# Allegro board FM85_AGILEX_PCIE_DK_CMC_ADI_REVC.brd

Outline 254 x 111.15 mm; copper layers: TOP, L02_GND1, L03_SIG1, L04_GND2, L05_SIG2, L06_GND3, L07_SIG3, L08_GND4, L09_PWR1, L10_PWR2, L11_GND5, L12_SIG4, L13_GND6, L14_SIG5, L15_GND7, L16_SIG6, L17_GND8, BOTTOM. Coordinates in mm from the lower left corner of the outline.
Outline path: 0,111.15 0,4.5 15,4.5 15,12.75 33.35,12.75 33.35,4.5 41.35,4.5 41.35,10.92 arc(43.18,12.75) 45,10.92 45,0.5 45.5,0 55.7,0 56.2,0.5 56.2,7.45 arc(57.15,8.4) 58.1,7.45 58.1,0.5 58.6,0 128.8,0 129.3,0.5 129.3,7.62 arc(130.67,8.99) 132.04,7.62 132.04,3.45 132.55,2.95 143.35,2.95 144.74,5.32 144.74,7.95 140.78,7.95 arc(139.54,8.46) 139.03,9.7 139.03,11 arc(139.54,12.24) 140.78,12.75 254,12.75 254,111.15 0,111.15

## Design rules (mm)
constraint set DEFAULT: min track width 0.149
net group AVST8_CLK: nets AVST8_CLK AVST8_CLK_R
net group BMC_BUF_TCK: nets BMC_BUF_TCK N40362434
net group BMC_BUF_TDI: nets BMC_BUF_TDI N40362458
net group BMC_BUF_TMS: nets BMC_BUF_TMS N40362320
net group BUF1_Q0_N: nets BUF1_Q0_N REFCLK_PCIE_14C_CH0_N
net group BUF1_Q0_P: nets BUF1_Q0_P REFCLK_PCIE_14C_CH0_P
net group BUF1_Q1_N: nets BUF1_Q1_N REFCLK_PCIE_14C_CH1_N
net group BUF1_Q1_P: nets BUF1_Q1_P REFCLK_PCIE_14C_CH1_P
net group BUF2_Q0_N: nets BUF2_Q0_N REFCLK_CXL_15C_CH0_N
net group BUF2_Q0_P: nets BUF2_Q0_P REFCLK_CXL_15C_CH0_P
net group BUF2_Q1_N: nets BUF2_Q1_N REFCLK_CXL_15C_CH1_N
net group BUF2_Q1_P: nets BUF2_Q1_P REFCLK_CXL_15C_CH1_P
net group BUF2_Q2_N: nets BUF2_Q2_N REFCLK_FM41_15C_CXL_N
net group BUF2_Q2_P: nets BUF2_Q2_P REFCLK_FM41_15C_CXL_P
net group CLK_DDR4: nets CLK_DDR4_CH1_N CLK_DDR4_CH1_P
net group CLK_DDR4_CH0_N: nets CLK_DDR4_CH0_N SI5391_OUT2N
net group CLK_DDR4_CH0_P: nets CLK_DDR4_CH0_P SI5391_OUT2P
net group CLK_DDR4_CH2_N: nets CLK_DDR4_CH2_N SI5391_OUT1N
net group CLK_DDR4_CH2_P: nets CLK_DDR4_CH2_P SI5391_OUT1P
net group CLK_SYS_100M_N: nets CLK_SYS_100M_N SI5391_OUT9N
net group CLK_SYS_100M_P: nets CLK_SYS_100M_P SI5391_OUT9P
net group CXL_TX_C_N0: nets CXL_TX_C_N0 CXL_TX_N0
net group CXL_TX_C_N1: nets CXL_TX_C_N1 CXL_TX_N1
net group CXL_TX_C_N2: nets CXL_TX_C_N2 CXL_TX_N2
net group CXL_TX_C_N3: nets CXL_TX_C_N3 CXL_TX_N3
net group CXL_TX_C_N4: nets CXL_TX_C_N4 CXL_TX_N4
net group CXL_TX_C_N5: nets CXL_TX_C_N5 CXL_TX_N5
net group CXL_TX_C_N6: nets CXL_TX_C_N6 CXL_TX_N6
net group CXL_TX_C_N7: nets CXL_TX_C_N7 CXL_TX_N7
net group CXL_TX_C_N8: nets CXL_TX_C_N8 CXL_TX_N8
net group CXL_TX_C_N9: nets CXL_TX_C_N9 CXL_TX_N9
net group CXL_TX_C_N10: nets CXL_TX_C_N10 CXL_TX_N10
net group CXL_TX_C_N11: nets CXL_TX_C_N11 CXL_TX_N11
net group CXL_TX_C_N12: nets CXL_TX_C_N12 CXL_TX_N12
net group CXL_TX_C_N13: nets CXL_TX_C_N13 CXL_TX_N13
net group CXL_TX_C_N14: nets CXL_TX_C_N14 CXL_TX_N14
net group CXL_TX_C_N15: nets CXL_TX_C_N15 CXL_TX_N15
net group CXL_TX_C_P0: nets CXL_TX_C_P0 CXL_TX_P0
net group CXL_TX_C_P1: nets CXL_TX_C_P1 CXL_TX_P1
net group CXL_TX_C_P2: nets CXL_TX_C_P2 CXL_TX_P2
net group CXL_TX_C_P3: nets CXL_TX_C_P3 CXL_TX_P3
net group CXL_TX_C_P4: nets CXL_TX_C_P4 CXL_TX_P4
net group CXL_TX_C_P5: nets CXL_TX_C_P5 CXL_TX_P5
net group CXL_TX_C_P6: nets CXL_TX_C_P6 CXL_TX_P6
net group CXL_TX_C_P7: nets CXL_TX_C_P7 CXL_TX_P7
net group CXL_TX_C_P8: nets CXL_TX_C_P8 CXL_TX_P8
net group CXL_TX_C_P9: nets CXL_TX_C_P9 CXL_TX_P9
net group CXL_TX_C_P10: nets CXL_TX_C_P10 CXL_TX_P10
net group CXL_TX_C_P11: nets CXL_TX_C_P11 CXL_TX_P11
net group CXL_TX_C_P12: nets CXL_TX_C_P12 CXL_TX_P12
net group CXL_TX_C_P13: nets CXL_TX_C_P13 CXL_TX_P13
net group CXL_TX_C_P14: nets CXL_TX_C_P14 CXL_TX_P14
net group CXL_TX_C_P15: nets CXL_TX_C_P15 CXL_TX_P15
net group DDR4_DDIMM2_C0: nets DDR4_DDIMM2_C0 DDR4_DDIMM2_C0_CS_N2
net group DDR4_DDIMM_C0: nets DDR4_DDIMM_C0 DDR4_DDIMM_C0_CS_N2
net group DP39: nets DDR4_DDIMM_CK_N1 DDR4_DDIMM_CK_P1
net group DP41: nets REFCLK_FM41_14C_PCIE_N REFCLK_FM41_14C_PCIE_P
net group DP_DDR3B_DQS_6: nets DDR4_COMP_CH0_DQS_P3 DDR4_DDIMM2_DQS_P1
net group DP_FX2_D_: nets FX2_D_N FX2_D_P
net group DP_N4110735: nets N41107356 N41107358
net group DP_PEX_RX_0: nets PCIE_EP_TX_N0 PCIE_EP_TX_P0
net group DP_PEX_RX_1: nets PCIE_EP_TX_N1 PCIE_EP_TX_P1
net group DP_PEX_RX_2: nets PCIE_EP_TX_N2 PCIE_EP_TX_P2
net group DP_PEX_RX_3: nets PCIE_EP_TX_N3 PCIE_EP_TX_P3
net group DP_PEX_RX_4: nets PCIE_EP_TX_N4 PCIE_EP_TX_P4
net group DP_PEX_RX_5: nets PCIE_EP_TX_N5 PCIE_EP_TX_P5
net group DP_PEX_RX_6: nets PCIE_EP_TX_N6 PCIE_EP_TX_P6
net group DP_PEX_RX_7: nets PCIE_EP_TX_N7 PCIE_EP_TX_P7
net group DP_PEX_RX_8: nets PCIE_EP_TX_N8 PCIE_EP_TX_P8
net group DP_PEX_RX_9: nets PCIE_EP_TX_N9 PCIE_EP_TX_P9
net group DP_PEX_RX_10: nets PCIE_EP_TX_N10 PCIE_EP_TX_P10
net group DP_PEX_RX_11: nets PCIE_EP_TX_N11 PCIE_EP_TX_P11
net group DP_PEX_RX_12: nets PCIE_EP_TX_N12 PCIE_EP_TX_P12
net group DP_PEX_RX_13: nets PCIE_EP_TX_N13 PCIE_EP_TX_P13
net group DP_PEX_RX_14: nets PCIE_EP_TX_N14 PCIE_EP_TX_P14
net group DP_PEX_RX_15: nets PCIE_EP_TX_N15 PCIE_EP_TX_P15
net group FM6_TEMP1: nets FPGA_TEMP1N FPGA_TEMP1P
net group FM6_TEMP3: nets FPGA_TEMP3N FPGA_TEMP3P
net group FPGA_TEMP0A: nets FPGA_TEMP0AN FPGA_TEMP0AP
net group FPGA_TEMP0C: nets FPGA_TEMP0CN FPGA_TEMP0CP
net group FPGA_TEMP4: nets FPGA_TEMP4N FPGA_TEMP4P
net group FPGA_TEMP6: nets FPGA_TEMP6N FPGA_TEMP6P
net group GNDSENSE: nets GNDSENSE VSENSE0-
net group HPS_OSC_CLK: nets HPS_OSC_CLK SI5391_OUT9A
net group HRAM_CK: nets HRAM_CK HRAM_CK_R
net group HRAM_CK_N: nets HRAM_CK_N HRAM_CK_N_R
net group HRAM_CS: nets HRAM_CS HRAM_CS_R
net group HRAM_D0: nets HRAM_D0 N46887455
net group HRAM_D1: nets HRAM_D1 N46887476
net group HRAM_D2: nets HRAM_D2 N46887502
net group HRAM_D3: nets HRAM_D3 N46887527
net group HRAM_D4: nets HRAM_D4 N46887553
net group HRAM_D5: nets HRAM_D5 N46887581
net group HRAM_D6: nets HRAM_D6 N46887604
net group HRAM_D7: nets HRAM_D7 N46887630
net group I2C2: nets I2C2_SCL I2C2_SDA
net group I2C3: nets I2C3_SCL I2C3_SDA
net group MG2: nets DDR4_DDIMM_CK_N0 DDR4_DDIMM_CK_P0
net group N32053041: nets N32052935 N32053041
net group N40226164: nets N40226161 N40226164
net group N40710315: nets N40710194 N40710315
net group N41064487: nets N41064487 N41064609
net group PCIE_EP_JTAG_TDO: nets N40362341 PCIE_EP_JTAG_TDO
net group PCIE_EP_RX_CN0: nets PCIE_EP_RX_CN0 PCIE_EP_RX_N0
net group PCIE_EP_RX_CN1: nets PCIE_EP_RX_CN1 PCIE_EP_RX_N1
net group PCIE_EP_RX_CN2: nets PCIE_EP_RX_CN2 PCIE_EP_RX_N2
net group PCIE_EP_RX_CN3: nets PCIE_EP_RX_CN3 PCIE_EP_RX_N3
net group PCIE_EP_RX_CN4: nets PCIE_EP_RX_CN4 PCIE_EP_RX_N4
net group PCIE_EP_RX_CN5: nets PCIE_EP_RX_CN5 PCIE_EP_RX_N5
net group PCIE_EP_RX_CN6: nets PCIE_EP_RX_CN6 PCIE_EP_RX_N6
net group PCIE_EP_RX_CN7: nets PCIE_EP_RX_CN7 PCIE_EP_RX_N7
net group PCIE_EP_RX_CN8: nets PCIE_EP_RX_CN8 PCIE_EP_RX_N8
net group PCIE_EP_RX_CN9: nets PCIE_EP_RX_CN9 PCIE_EP_RX_N9
net group PCIE_EP_RX_CN10: nets PCIE_EP_RX_CN10 PCIE_EP_RX_N10
net group PCIE_EP_RX_CN11: nets PCIE_EP_RX_CN11 PCIE_EP_RX_N11
net group PCIE_EP_RX_CN12: nets PCIE_EP_RX_CN12 PCIE_EP_RX_N12
net group PCIE_EP_RX_CN13: nets PCIE_EP_RX_CN13 PCIE_EP_RX_N13
net group PCIE_EP_RX_CN14: nets PCIE_EP_RX_CN14 PCIE_EP_RX_N14
net group PCIE_EP_RX_CN15: nets PCIE_EP_RX_CN15 PCIE_EP_RX_N15
net group PCIE_EP_RX_CP0: nets PCIE_EP_RX_CP0 PCIE_EP_RX_P0
net group PCIE_EP_RX_CP1: nets PCIE_EP_RX_CP1 PCIE_EP_RX_P1
net group PCIE_EP_RX_CP2: nets PCIE_EP_RX_CP2 PCIE_EP_RX_P2
net group PCIE_EP_RX_CP3: nets PCIE_EP_RX_CP3 PCIE_EP_RX_P3
net group PCIE_EP_RX_CP4: nets PCIE_EP_RX_CP4 PCIE_EP_RX_P4
net group PCIE_EP_RX_CP5: nets PCIE_EP_RX_CP5 PCIE_EP_RX_P5
net group PCIE_EP_RX_CP6: nets PCIE_EP_RX_CP6 PCIE_EP_RX_P6
net group PCIE_EP_RX_CP7: nets PCIE_EP_RX_CP7 PCIE_EP_RX_P7
net group PCIE_EP_RX_CP8: nets PCIE_EP_RX_CP8 PCIE_EP_RX_P8
net group PCIE_EP_RX_CP9: nets PCIE_EP_RX_CP9 PCIE_EP_RX_P9
net group PCIE_EP_RX_CP10: nets PCIE_EP_RX_CP10 PCIE_EP_RX_P10
net group PCIE_EP_RX_CP11: nets PCIE_EP_RX_CP11 PCIE_EP_RX_P11
net group PCIE_EP_RX_CP12: nets PCIE_EP_RX_CP12 PCIE_EP_RX_P12
net group PCIE_EP_RX_CP13: nets PCIE_EP_RX_CP13 PCIE_EP_RX_P13
net group PCIE_EP_RX_CP14: nets PCIE_EP_RX_CP14 PCIE_EP_RX_P14
net group PCIE_EP_RX_CP15: nets PCIE_EP_RX_CP15 PCIE_EP_RX_P15
net group REFCLK_CXL_RP_N0: nets REFCLK_CXL_RP_N0 SI2204_OUT2N
net group REFCLK_CXL_RP_N1: nets REFCLK_CXL_RP_N1 SI2204_OUT3N
net group REFCLK_CXL_RP_P0: nets REFCLK_CXL_RP_P0 SI2204_OUT2P
net group REFCLK_CXL_RP_P1: nets REFCLK_CXL_RP_P1 SI2204_OUT3P
net group REFCLK_FGT12ACH0_N: nets REFCLK_FGT12ACH0_N SI5391_OUT8N
net group REFCLK_FGT12ACH0_P: nets REFCLK_FGT12ACH0_P SI5391_OUT8P
net group REFCLK_FGT12ACH3_N: nets REFCLK_FGT12ACH3_N SI5391_OUT6N
net group REFCLK_FGT12ACH3_P: nets REFCLK_FGT12ACH3_P SI5391_OUT6P
net group REFCLK_FGT12ACH4_N: nets REFCLK_FGT12ACH4_N SI5391_OUT0N
net group REFCLK_FGT12ACH4_P: nets REFCLK_FGT12ACH4_P SI5391_OUT0P
net group REFCLK_FGT12ACH5_N: nets REFCLK_FGT12ACH5_N SI5391_OUT0AN
net group REFCLK_FGT12ACH5_P: nets REFCLK_FGT12ACH5_P SI5391_OUT0AP
net group REFCLK_FGT12ACH6_N: nets REFCLK_FGT12ACH6_N SI5391_OUT4N
net group REFCLK_FGT12ACH6_P: nets REFCLK_FGT12ACH6_P SI5391_OUT4P
net group REFCLK_PCIE_EP_EDGE_N: nets BUF1_CLK0_N REFCLK_PCIE_EP_EDGE_N
net group REFCLK_PCIE_EP_EDGE_P: nets BUF1_CLK0_P REFCLK_PCIE_EP_EDGE_P
net group USB_T_CLK: nets N49230785 USB_T_CLK
net group VCCED_SNS_P: nets VCCED_SNS_N VCCED_SNS_P
net group VCCL_HPS_SNS_P: nets VCCL_HPS_SNS_N VCCL_HPS_SNS_P
net group VCCLSENSE: nets VCCLSENSE VSENSE0+
net group 5MILS: nets 1P2V_DDR4_CH01_PG 1P8V_EN 1P8V_PG 2P5V_EN 2P5V_PG 3P3V_EN 3P3V_PG 5V_PG 12V_G1_OV_PG 12V_G1_PG 12V_G1_UV_PG 12V_G2_PG FPGA_I2C_EN FPGA_PMBUS_EN FPGA_VCC_EN FPGA_VCC_PG IO_1P8V_EN IO_1P8V_PG IO_3P3V_EN MAIN_PMBUS_EN VCCFUSEWR_EN VCCFUSEWR_PG VCCL_HPS_EN VCCL_HPS_PG
net group 8MILS: nets N32408441 N40710340 N45054348 N45054411 N45054431 N45054433 N45054466 N45054537 N45054575 N45054598 N45054651 N45054838 N45056577 N45056642 N45056662 N45056664 N45056697 N45056806 N45056829 N45056882 N45057066
net group 12V_PWR: nets 12V_AUX 12V_G2 12V_GROUP1 12V_GROUP2 PCIE_EP_12V
net group 42.5 OHM OUT: nets N37651435 N37651438 N37651441 N37651444 N37651447 N37651450 N37651453 N37651456 N37651459 N37651462 N37651465 PCIE_CLKREQN PCIE_EP_PRSNT_NX1 PCIE_EP_PRSNT_NX4 PCIE_EP_PRSNT_NX8 PCIE_EP_PRSNT_NX16 PCIE_PWRBRKN PCIE_RSV2 PCIE_RSV4 PCIE_RSV5 PCIE_RSV6 PCIE_RSV7
net group BUF1_CLK1_N: nets BUF1_CLK1_N REFCLK_PCIE_EP_N SI2204_OUT0N
net group BUF1_CLK1_P: nets BUF1_CLK1_P REFCLK_PCIE_EP_P SI2204_OUT0P
net group BUF2_CLK0_N: nets BUF2_CLK0_N CLK_100M_CXL_CONN_C_N CLK_CXL_CONN_N
net group BUF2_CLK0_P: nets BUF2_CLK0_P CLK_100M_CXL_CONN_C_P CLK_CXL_CONN_P
net group BUF2_CLK1_N: nets BUF2_CLK1_N REFCLK_CXL_EP_N SI2204_OUT1N
net group BUF2_CLK1_P: nets BUF2_CLK1_P REFCLK_CXL_EP_P SI2204_OUT1P
net group CLK: nets SI5391_OUT3N SI5391_OUT3P SI5391_OUT5N SI5391_OUT5P
net group CLK_SE: nets DDR4_DIMM_SCL DDR4_DIMM_SDA FPGA_OSC_CLK_1 FPGA_SDM_SCL FPGA_SDM_SDA PCIE_1V2_CLKREQN PCIE_EP_SMBCLK SEL_CXL_REFCLK SEL_PCIE_REFCLK
net group CXL_RX: nets CXL_RX_N0 CXL_RX_N1 CXL_RX_N2 CXL_RX_N3 CXL_RX_N5 CXL_RX_N6 CXL_RX_N7 CXL_RX_N9 CXL_RX_N10 CXL_RX_N11 CXL_RX_N12 CXL_RX_N13 CXL_RX_N15 CXL_RX_P0 CXL_RX_P1 CXL_RX_P2 CXL_RX_P3 CXL_RX_P5 CXL_RX_P6 CXL_RX_P7 CXL_RX_P9 CXL_RX_P10 CXL_RX_P11 CXL_RX_P12 CXL_RX_P13 CXL_RX_P15
net group DDR: nets DDR4_COMP_CH0_A1 DDR4_COMP_CH0_A2 DDR4_COMP_CH0_A3 DDR4_COMP_CH0_A4 DDR4_COMP_CH0_A5 DDR4_COMP_CH0_A6 DDR4_COMP_CH0_A7 DDR4_COMP_CH0_A8 DDR4_COMP_CH0_A9 DDR4_COMP_CH0_A10 DDR4_COMP_CH0_A11 DDR4_COMP_CH0_A12 DDR4_COMP_CH0_A13 DDR4_COMP_CH0_A14 DDR4_COMP_CH0_A15 DDR4_COMP_CH0_A16 DDR4_COMP_CH0_ACT_N DDR4_COMP_CH0_ALERT_N DDR4_COMP_CH0_BA0 DDR4_COMP_CH0_BA1 DDR4_COMP_CH0_BG0 DDR4_COMP_CH0_BG1 DDR4_COMP_CH0_CLK_N DDR4_COMP_CH0_CS_N DDR4_COMP_CH0_DBI_N0 DDR4_COMP_CH0_DBI_N1 DDR4_COMP_CH0_DBI_N2 DDR4_COMP_CH0_DBI_N3 DDR4_COMP_CH0_DBI_N4 DDR4_COMP_CH0_DBI_N5 DDR4_COMP_CH0_DBI_N6 DDR4_COMP_CH0_DBI_N7 DDR4_COMP_CH0_DBI_N8 DDR4_COMP_CH0_DQ0 DDR4_COMP_CH0_DQ1 DDR4_COMP_CH0_DQ2 DDR4_COMP_CH0_DQ3 DDR4_COMP_CH0_DQ4 DDR4_COMP_CH0_DQ5 DDR4_COMP_CH0_DQ6 DDR4_COMP_CH0_DQ7 DDR4_COMP_CH0_DQ8 DDR4_COMP_CH0_DQ9 DDR4_COMP_CH0_DQ10 DDR4_COMP_CH0_DQ11 DDR4_COMP_CH0_DQ12 DDR4_COMP_CH0_DQ13 DDR4_COMP_CH0_DQ14 DDR4_COMP_CH0_DQ15 DDR4_COMP_CH0_DQ16 DDR4_COMP_CH0_DQ17 DDR4_COMP_CH0_DQ18 DDR4_COMP_CH0_DQ19 DDR4_COMP_CH0_DQ20 DDR4_COMP_CH0_DQ21 DDR4_COMP_CH0_DQ22 DDR4_COMP_CH0_DQ23 DDR4_COMP_CH0_DQ24 DDR4_COMP_CH0_DQ25 DDR4_COMP_CH0_DQ26 DDR4_COMP_CH0_DQ27 DDR4_COMP_CH0_DQ28 DDR4_COMP_CH0_DQ29 DDR4_COMP_CH0_DQ30 DDR4_COMP_CH0_DQ31 DDR4_COMP_CH0_DQ32 DDR4_COMP_CH0_DQ33 DDR4_COMP_CH0_DQ34 DDR4_COMP_CH0_DQ35 DDR4_COMP_CH0_DQ36 DDR4_COMP_CH0_DQ37 DDR4_COMP_CH0_DQ38 DDR4_COMP_CH0_DQ39 DDR4_COMP_CH0_DQ40 DDR4_COMP_CH0_DQ41 DDR4_COMP_CH0_DQ42 DDR4_COMP_CH0_DQ43 DDR4_COMP_CH0_DQ44 DDR4_COMP_CH0_DQ45 DDR4_COMP_CH0_DQ46 DDR4_COMP_CH0_DQ47 DDR4_COMP_CH0_DQ48 DDR4_COMP_CH0_DQ49 DDR4_COMP_CH0_DQ50 DDR4_COMP_CH0_DQ51 DDR4_COMP_CH0_DQ52 DDR4_COMP_CH0_DQ53 DDR4_COMP_CH0_DQ54 DDR4_COMP_CH0_DQ55 DDR4_COMP_CH0_DQ56 DDR4_COMP_CH0_DQ57 DDR4_COMP_CH0_DQ58 DDR4_COMP_CH0_DQ59 DDR4_COMP_CH0_DQ60 DDR4_COMP_CH0_DQ61 DDR4_COMP_CH0_DQ62 DDR4_COMP_CH0_DQ63 DDR4_COMP_CH0_DQ64 DDR4_COMP_CH0_DQ65 DDR4_COMP_CH0_DQ66 DDR4_COMP_CH0_DQ67 DDR4_COMP_CH0_DQ68 DDR4_COMP_CH0_DQ69 DDR4_COMP_CH0_DQ70 DDR4_COMP_CH0_DQ71 DDR4_COMP_CH0_DQS_N0 DDR4_COMP_CH0_DQS_N1 DDR4_COMP_CH0_DQS_N2 DDR4_COMP_CH0_DQS_N3 DDR4_COMP_CH0_DQS_N4 DDR4_COMP_CH0_DQS_N5 DDR4_COMP_CH0_DQS_N6 DDR4_COMP_CH0_DQS_N7 DDR4_COMP_CH0_DQS_N8 DDR4_COMP_CH0_DQS_P0 DDR4_COMP_CH0_DQS_P1 DDR4_COMP_CH0_DQS_P2 DDR4_COMP_CH0_DQS_P4 DDR4_COMP_CH0_DQS_P5 DDR4_COMP_CH0_DQS_P6 DDR4_COMP_CH0_DQS_P7 DDR4_COMP_CH0_DQS_P8 DDR4_COMP_CH0_ODT DDR4_COMP_CH0_PAR DDR4_COMP_CH0_RZQ DDR4_COMP_CH0_TEN DDR4_COMP_CH1_DBI_N0 DDR4_COMP_CH1_DBI_N1 DDR4_COMP_CH1_DBI_N2 DDR4_COMP_CH1_DBI_N3 DDR4_COMP_CH1_DBI_N4 DDR4_COMP_CH1_DBI_N5 DDR4_COMP_CH1_DBI_N6 DDR4_COMP_CH1_DBI_N7 DDR4_COMP_CH1_DBI_N8 DDR4_COMP_CH1_DQ0 DDR4_COMP_CH1_DQ1 DDR4_COMP_CH1_DQ2 DDR4_COMP_CH1_DQ3 DDR4_COMP_CH1_DQ4 DDR4_COMP_CH1_DQ5 DDR4_COMP_CH1_DQ6 DDR4_COMP_CH1_DQ7 DDR4_COMP_CH1_DQ8 DDR4_COMP_CH1_DQ9 DDR4_COMP_CH1_DQ10 DDR4_COMP_CH1_DQ11 DDR4_COMP_CH1_DQ12 DDR4_COMP_CH1_DQ13 DDR4_COMP_CH1_DQ14 DDR4_COMP_CH1_DQ15 DDR4_COMP_CH1_DQ16 DDR4_COMP_CH1_DQ17 DDR4_COMP_CH1_DQ18 DDR4_COMP_CH1_DQ19 DDR4_COMP_CH1_DQ20 DDR4_COMP_CH1_DQ21 DDR4_COMP_CH1_DQ22 DDR4_COMP_CH1_DQ23 DDR4_COMP_CH1_DQ24 DDR4_COMP_CH1_DQ25 DDR4_COMP_CH1_DQ26 DDR4_COMP_CH1_DQ27 DDR4_COMP_CH1_DQ28 DDR4_COMP_CH1_DQ29 DDR4_COMP_CH1_DQ30 DDR4_COMP_CH1_DQ31 DDR4_COMP_CH1_DQ32 DDR4_COMP_CH1_DQ33 DDR4_COMP_CH1_DQ34 DDR4_COMP_CH1_DQ35 DDR4_COMP_CH1_DQ36 DDR4_COMP_CH1_DQ37 DDR4_COMP_CH1_DQ38 DDR4_COMP_CH1_DQ39 DDR4_COMP_CH1_DQ40 DDR4_COMP_CH1_DQ41 DDR4_COMP_CH1_DQ42 DDR4_COMP_CH1_DQ43 DDR4_COMP_CH1_DQ44 DDR4_COMP_CH1_DQ45 DDR4_COMP_CH1_DQ46 DDR4_COMP_CH1_DQ47 DDR4_COMP_CH1_DQ48 DDR4_COMP_CH1_DQ49 DDR4_COMP_CH1_DQ50 DDR4_COMP_CH1_DQ51 DDR4_COMP_CH1_DQ52 DDR4_COMP_CH1_DQ53 DDR4_COMP_CH1_DQ54 DDR4_COMP_CH1_DQ55 DDR4_COMP_CH1_DQ56 DDR4_COMP_CH1_DQ57 DDR4_COMP_CH1_DQ58 DDR4_COMP_CH1_DQ59 DDR4_COMP_CH1_DQ60 DDR4_COMP_CH1_DQ61 DDR4_COMP_CH1_DQ62 DDR4_COMP_CH1_DQ63 DDR4_COMP_CH1_DQ64 DDR4_COMP_CH1_DQ65 DDR4_COMP_CH1_DQ66 DDR4_COMP_CH1_DQ67 DDR4_COMP_CH1_DQ68 DDR4_COMP_CH1_DQ69 DDR4_COMP_CH1_DQ70 DDR4_COMP_CH1_DQ71 DDR4_COMP_CH1_DQS_N0 DDR4_COMP_CH1_DQS_N1 DDR4_COMP_CH1_DQS_N2 DDR4_COMP_CH1_DQS_N3 DDR4_COMP_CH1_DQS_N4 DDR4_COMP_CH1_DQS_N5 DDR4_COMP_CH1_DQS_N6 DDR4_COMP_CH1_DQS_N7 DDR4_COMP_CH1_DQS_N8 DDR4_COMP_CH1_DQS_P0 DDR4_COMP_CH1_DQS_P1 DDR4_COMP_CH1_DQS_P2 DDR4_COMP_CH1_DQS_P3 DDR4_COMP_CH1_DQS_P4 DDR4_COMP_CH1_DQS_P5 DDR4_COMP_CH1_DQS_P6 DDR4_COMP_CH1_DQS_P7 DDR4_COMP_CH1_DQS_P8 DDR4_COMP_CH1_RZQ DDR4_COMP_CH1_TEN
net group DDR4_DDIMM2_C1: nets DDR4_DDIMM2_C1
net group DDR4_DDIMM_C1: nets DDR4_DDIMM_C1 DDR4_DDIMM_C1_CS_N3 DDR4_DDIMM_CS_N3
net group DDR4_DIMM_ADDR: nets DDR4_DDIMM_EVENT_N DDR4_DDIMM_RZQ DDR4_DDIMM_SA0 DDR4_DDIMM_SA1 DDR4_DDIMM_SA2 DDR4_DDIMM_SAVE_N
net group EXT_JTAG_TCK: nets N403487415
net group GATE: nets N32230759 N32232827 N32233406 N36348634
net group HRAM_L: nets HRAM_RWDS
net group JTAG_USB: nets USB_MAX_TCK USB_MAX_TDI USB_MAX_TDO USB_MAX_TMS
net group LOW_NOISE: nets 1P2V_DDR4_CH2_AGND 6301_AGND ADC_VREF AGND_1P2V_PRE AGND_2P5V_PRE AGND_3P3V_STBY AGND_VCCFUSEWR_SDM INTVCC_PVCC IO_1P8V_AGND LTM4623_INTVCC LTM4623_INTVCC1 LTM4623_INTVCC2 LTM4623_INTVCC3 LTM4623_INTVCC4 LTM4623_INTVCC5 M10_VCCINT MAX10_VCCA_ADC_2.5V N28015562 N28022993 N30715060 N30715756 N36316148 N36316589 N39073276 N39073371 N39075525 N39075684 N46986379 SVIN4 SVIN5 VBUS_5V VCC_INT VCCL_HPS_AGND VOSNS0_0P8V
net group MG1: nets DDR4_DIMM2_CK_N0 DDR4_DIMM2_CK_N1 DDR4_DIMM2_CK_P0 DDR4_DIMM2_CK_P1
net group QSFPDD: nets QSFPDD0_RX1_N QSFPDD0_RX1_P QSFPDD0_RX2_N QSFPDD0_RX2_P QSFPDD0_RX3_N QSFPDD0_RX3_P QSFPDD0_RX4_N QSFPDD0_RX4_P QSFPDD0_RX5_N QSFPDD0_RX5_P QSFPDD0_RX6_N QSFPDD0_RX6_P QSFPDD0_RX7_N QSFPDD0_RX7_P QSFPDD0_TX0_N QSFPDD0_TX0_P QSFPDD0_TX1_N QSFPDD0_TX1_P QSFPDD0_TX2_N QSFPDD0_TX2_P QSFPDD0_TX3_N QSFPDD0_TX3_P QSFPDD0_TX4_N QSFPDD0_TX4_P QSFPDD0_TX5_N QSFPDD0_TX5_P QSFPDD0_TX6_N QSFPDD0_TX6_P QSFPDD0_TX7_N QSFPDD0_TX7_P QSFPDD1_RX1_N QSFPDD1_RX1_P QSFPDD1_RX3_N QSFPDD1_RX3_P QSFPDD1_RX4_N QSFPDD1_RX4_P QSFPDD1_RX5_N QSFPDD1_RX5_P QSFPDD1_RX6_N QSFPDD1_RX6_P QSFPDD1_RX7_N QSFPDD1_RX7_P QSFPDD1_TX0_N QSFPDD1_TX0_P QSFPDD1_TX1_N QSFPDD1_TX1_P QSFPDD1_TX2_N QSFPDD1_TX2_P QSFPDD1_TX3_N QSFPDD1_TX3_P QSFPDD1_TX4_N QSFPDD1_TX4_P QSFPDD1_TX5_N QSFPDD1_TX5_P QSFPDD1_TX6_N QSFPDD1_TX6_P QSFPDD1_TX7_N QSFPDD1_TX7_P
nets with their own width: min track width 0.381; nets N32230321

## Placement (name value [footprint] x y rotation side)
B1  Molex_QSFPDD_Cage  [MOLEX_QSFPDD_CAGE]  40.1 90.54 90 top
B2  Molex_QSFPDD_Cage  [MOLEX_QSFPDD_CAGE]  40.1 65.75 90 top
C1  0.1uF  [0402]  89.33 19.74 180 bottom
C2  0.1uF  [0402]  109.65 19.74 180 bottom
C3  0.47uF  [0402]  96.14 17.8 270 bottom
C4  0.47uF  [0402]  89.74 28.1 270 bottom
C5  22uF  [0603]  92.54 26.19 270 bottom
C6  0.47uF  [0402]  116.46 17.81 270 bottom
C7  0.47uF  [0402]  110.06 28.12 270 bottom
C8  22uF  [0603]  113.24 26.21 270 bottom
C9  2.2nF  [0402]  115.26 24.53 180 bottom
C10  2.2nF  [0402]  89.33 17.34 180 bottom
C11  2.2nF  [0402]  109.65 17.34 180 bottom
C12  2.2nF  [0402]  94.94 24.54 180 bottom
C13  2.2nF  [0402]  89.74 26.4 270 bottom
C14  2.2nF  [0402]  96.14 20.86 270 bottom
C15  2.2nF  [0402]  110.06 26.42 270 bottom
C16  2.2nF  [0402]  95.33 29.05 90 bottom
C17  2.2nF  [0402]  116.46 20.88 270 bottom
C18  3.3nF  [0402]  89.74 25 90 bottom
C19  3.3nF  [0402]  110.06 25.02 90 bottom
C20  4.7nF  [0402]  109.26 21.02 90 bottom
C21  4.7nF  [0402]  88.88 21.01 90 bottom
C22  4.7nF  [0402]  95.33 26.62 90 bottom
C23  0.47uF  [0402]  91.46 28.1 270 bottom
C24  0.47uF  [0402]  93.64 24.2 90 bottom
C25  0.47uF  [0402]  96.2 28.1 270 bottom
C26  22uF  [0603]  112.83 22.23 90 bottom
C27  22uF  [0603]  92.51 22.21 90 bottom
C28  1uF  [0402]  96.74 23.96 270 bottom
C29  1uF  [0402]  117.06 23.92 270 bottom
C30  0.01uF  [0402]  96.2 22.53 270 bottom
C31  0.01uF  [0402]  115.65 29.02 90 bottom
C32  0.01uF  [0402]  116.46 22.61 270 bottom
C33  0.1uF  [0402]  88.94 27.3 90 bottom
C34  0.1uF  [0402]  110.06 29.07 270 bottom
C35  0.1uF  [0402]  109.26 27.29 90 bottom
C36  0.1uF  [0402]  89.74 29 270 bottom
C37  0.47uF  [0402]  109.23 24.06 90 bottom
C38  0.47uF  [0402]  113.96 24.22 90 bottom
C39  0.47uF  [0402]  115.65 26.64 90 bottom
C40  0.47uF  [0402]  109.15 22.53 90 bottom
C41  0.47uF  [0402]  88.94 24 90 bottom
C42  0.47uF  [0402]  88.88 22.53 90 bottom
C43  0.47uF  [0402]  111.78 28.12 270 bottom
C44  0.47uF  [0402]  116.46 28.12 270 bottom
C45  0.47uF  [0402]  116.46 16.92 270 bottom
C46  0.47uF  [0402]  96.14 16.9 270 bottom
C47  0.1uF  [0402]  78.67 19.66 180 bottom
C48  0.1uF  [0402]  99.49 19.74 180 bottom
C49  0.47uF  [0402]  85.98 17.8 270 bottom
C50  0.47uF  [0402]  79.58 28.1 270 bottom
C51  22uF  [0603]  82.38 26.19 270 bottom
C52  0.47uF  [0402]  99.9 28.1 270 bottom
C53  0.47uF  [0402]  106.3 17.67 270 bottom
C54  22uF  [0603]  102.7 26.19 270 bottom
C55  2.2nF  [0402]  106.33 21.01 270 bottom
C56  2.2nF  [0402]  99.49 17.33 180 bottom
C57  2.2nF  [0402]  99.9 26.4 270 bottom
C58  2.2nF  [0402]  85.17 29 90 bottom
C59  2.2nF  [0402]  85.98 20.86 270 bottom
C60  2.2nF  [0402]  84.78 24.54 180 bottom
C61  2.2nF  [0402]  79.17 17.33 180 bottom
C62  2.2nF  [0402]  105.1 24.54 180 bottom
C63  2.2nF  [0402]  79.58 26.4 270 bottom
C64  3.3nF  [0402]  79.58 25 90 bottom
C65  3.3nF  [0402]  99.9 25 90 bottom
C66  4.7nF  [0402]  99.02 21.01 90 bottom
C67  4.7nF  [0402]  85.17 26.59 90 bottom
C68  4.7nF  [0402]  79.2 21.34 0 bottom
C69  0.47uF  [0402]  81.3 28.1 270 bottom
C70  0.47uF  [0402]  106.3 28.1 270 bottom
C71  0.47uF  [0402]  106.3 16.77 270 bottom
C72  22uF  [0603]  82.35 22.21 90 bottom
C73  22uF  [0603]  102.67 22.21 90 bottom
C74  1uF  [0402]  86.58 23.91 270 bottom
C75  1uF  [0402]  106.9 24.11 270 bottom
C76  0.01uF  [0402]  105.49 29 90 bottom
C77  0.01uF  [0402]  106.41 22.61 270 bottom
C78  0.01uF  [0402]  85.98 22.59 270 bottom
C79  0.1uF  [0402]  99.1 27.24 90 bottom
C80  0.1uF  [0402]  79.58 29 270 bottom
C81  0.1uF  [0402]  78.78 27.24 90 bottom
C82  0.1uF  [0402]  99.9 28.89 270 bottom
C83  0.47uF  [0402]  78.78 24 90 bottom
C84  0.47uF  [0402]  105.49 26.67 90 bottom
C85  0.47uF  [0402]  103.8 24.2 90 bottom
C86  0.47uF  [0402]  99.02 24.06 90 bottom
C87  0.47uF  [0402]  85.98 16.9 270 bottom
C88  0.47uF  [0402]  83.48 24.2 90 bottom
C89  0.47uF  [0402]  78.78 22.59 90 bottom
C90  0.47uF  [0402]  101.62 28.1 270 bottom
C91  0.47uF  [0402]  99.02 22.53 90 bottom
C92  0.47uF  [0402]  85.98 28.1 270 bottom
C93  0.1uF  [0402]  67.49 20.13 90 bottom
C94  0.47uF  [0402]  69.4 28.14 270 bottom
C95  0.47uF  [0402]  75.85 17.73 270 bottom
C96  22uF  [0603]  67.82 25.47 90 bottom
C97  100uF  [1206]  78.75 14.15 90 bottom
C98  0.01uF  [0402]  72.02 24.58 0 bottom
C99  0.1uF  [0402]  122.91 19.66 180 bottom
C100  0.1uF  [0402]  133.07 19.66 180 bottom
C101  0.47uF  [0402]  133.43 28.07 270 bottom
C102  0.47uF  [0402]  139.87 17.76 270 bottom
C103  22uF  [0603]  136.27 26.16 270 bottom
C104  0.47uF  [0402]  123.27 28.07 270 bottom
C105  0.47uF  [0402]  129.71 17.76 270 bottom
C106  22uF  [0603]  126.11 26.16 270 bottom
C107  2.2nF  [0402]  139.87 20.83 270 bottom
C108  2.2nF  [0402]  133.07 17.26 180 bottom
C109  2.2nF  [0402]  138.68 24.46 180 bottom
C110  2.2nF  [0402]  128.87 28.97 90 bottom
C111  2.2nF  [0402]  128.52 24.46 180 bottom
C112  2.2nF  [0402]  123.26 26.36 270 bottom
C113  2.2nF  [0402]  122.91 17.26 180 bottom
C114  2.2nF  [0402]  133.42 26.36 270 bottom
C115  2.2nF  [0402]  129.71 20.83 270 bottom
C116  3.3nF  [0402]  123.26 24.97 90 bottom
C117  3.3nF  [0402]  133.42 24.97 90 bottom
C118  4.7nF  [0402]  132.63 20.97 90 bottom
C119  4.7nF  [0402]  128.87 26.56 90 bottom
C120  4.7nF  [0402]  122.47 20.97 90 bottom
C121  0.47uF  [0402]  127.21 24.17 90 bottom
C122  0.47uF  [0402]  139.87 16.86 270 bottom
C123  0.47uF  [0402]  135.19 28.07 270 bottom
C124  22uF  [0603]  126.08 22.18 90 bottom
C125  22uF  [0603]  136.24 22.18 90 bottom
C126  1uF  [0402]  140.47 23.87 270 bottom
C127  1uF  [0402]  130.31 23.87 270 bottom
C128  0.01uF  [0402]  139.03 28.97 90 bottom
C129  0.01uF  [0402]  139.87 22.56 270 bottom
C130  0.01uF  [0402]  129.71 22.56 270 bottom
C131  0.1uF  [0402]  133.43 28.97 270 bottom
C132  0.1uF  [0402]  122.47 27.24 90 bottom
C133  0.1uF  [0402]  123.27 28.97 270 bottom
C134  0.1uF  [0402]  132.63 27.24 90 bottom
C135  0.47uF  [0402]  122.47 23.97 90 bottom
C136  0.47uF  [0402]  139.03 26.56 90 bottom
C137  0.47uF  [0402]  139.87 28.07 270 bottom
C138  0.47uF  [0402]  129.71 16.86 270 bottom
C139  0.47uF  [0402]  129.71 28.07 270 bottom
C140  0.47uF  [0402]  125.03 28.07 270 bottom
C141  0.47uF  [0402]  122.47 22.46 90 bottom
C142  0.47uF  [0402]  132.63 22.46 90 bottom
C143  0.47uF  [0402]  137.37 24.17 90 bottom
C144  0.47uF  [0402]  132.63 23.97 90 bottom
C145  0.1uF  [0402]  143.23 19.66 180 bottom
C146  0.1uF  [0402]  153.39 19.66 180 bottom
C147  0.47uF  [0402]  143.59 28.07 270 bottom
C148  0.47uF  [0402]  150.03 17.76 270 bottom
C149  22uF  [0603]  146.43 26.16 270 bottom
C150  0.47uF  [0402]  153.75 28.07 270 bottom
C151  0.47uF  [0402]  160.19 17.76 270 bottom
C152  22uF  [0603]  156.59 26.16 270 bottom
C153  2.2nF  [0402]  148.84 24.46 180 bottom
C154  2.2nF  [0402]  149.19 28.97 90 bottom
C155  2.2nF  [0402]  153.74 26.36 270 bottom
C156  2.2nF  [0402]  143.58 26.36 270 bottom
C157  2.2nF  [0402]  150.03 20.83 270 bottom
C158  2.2nF  [0402]  159.82 21.26 0 bottom
C159  2.2nF  [0402]  143.23 17.26 180 bottom
C160  2.2nF  [0402]  159 24.46 180 bottom
C161  2.2nF  [0402]  153.39 17.26 180 bottom
C162  3.3nF  [0402]  143.58 24.97 90 bottom
C163  3.3nF  [0402]  153.74 24.97 90 bottom
C164  4.7nF  [0402]  142.79 20.97 90 bottom
C165  4.7nF  [0402]  152.95 20.97 90 bottom
C166  4.7nF  [0402]  149.19 26.56 90 bottom
C167  0.47uF  [0402]  145.35 28.07 270 bottom
C168  0.47uF  [0402]  150.03 28.07 270 bottom
C169  0.47uF  [0402]  160.19 28.07 270 bottom
C170  22uF  [0603]  146.4 22.18 90 bottom
C171  22uF  [0603]  156.56 22.18 90 bottom
C172  1uF  [0402]  160.34 23.95 270 bottom
C173  1uF  [0402]  150.63 23.87 270 bottom
C174  0.01uF  [0402]  150.03 22.56 270 bottom
C175  0.01uF  [0402]  159.35 28.97 90 bottom
C176  0.01uF  [0402]  158.53 22.46 90 bottom
C177  0.1uF  [0402]  153.75 28.97 270 bottom
C178  0.1uF  [0402]  152.95 27.24 90 bottom
C179  0.1uF  [0402]  143.59 28.97 270 bottom
C180  0.1uF  [0402]  142.79 27.24 90 bottom
C181  0.47uF  [0402]  147.53 24.17 90 bottom
C182  0.47uF  [0402]  150.03 16.86 270 bottom
C183  0.47uF  [0402]  142.79 23.97 90 bottom
C184  0.47uF  [0402]  142.79 22.46 90 bottom
C185  0.47uF  [0402]  152.95 23.97 90 bottom
C186  0.47uF  [0402]  157.69 24.17 90 bottom
C187  0.47uF  [0402]  160.19 16.86 270 bottom
C188  0.47uF  [0402]  152.95 22.46 90 bottom
C189  0.47uF  [0402]  159.35 26.56 90 bottom
C190  0.47uF  [0402]  155.51 28.07 270 bottom
C191  0.1uF  [0402]  162.01 20.06 90 bottom
C192  0.47uF  [0402]  170.31 17.46 270 bottom
C193  22uF  [0603]  162.34 25.4 90 bottom
C194  0.47uF  [0402]  163.91 28.07 270 bottom
C195  100uF  [1206]  174 15.04 180 bottom
C196  0.01uF  [0402]  166.53 24.51 0 bottom
C197  1uF  [0402]  96.57 104.02 0 bottom
C198  0.1uF  [0402]  95.68 104.02 0 bottom
C199  0.1uF  [0402]  94.71 95.76 270 bottom
C200  10nF  [0402]  113.32 95.15 0 bottom
C201  0.1uF  [0402]  113.34 97.68 180 bottom
C202  10nF  [0402]  122.41 97.54 180 bottom
C203  0.1uF  [0402]  138.82 94.87 0 bottom
C204  10nF  [0402]  144.84 97.79 180 bottom
C205  0.1uF  [0402]  134.58 94.9 0 bottom
C206  10nF  [0402]  143.92 94.82 0 bottom
C207  0.1uF  [0402]  138.49 97.82 180 bottom
C208  10nF  [0402]  143.57 97.82 180 bottom
C209  0.1uF  [0402]  132.04 97.67 180 bottom
C210  10nF  [0402]  122.8 94.9 0 bottom
C211  0.1uF  [0402]  115.07 96.32 180 bottom
C212  100uF  [1206]  129.52 95.35 90 bottom
C213  1uF  [0402]  130.79 98.2 90 bottom
C214  0.1uF  [0402]  194.49 93.41 90 bottom
C215  0.1uF  [0402]  130.75 99.22 90 bottom
C216  100uF  [1206]  149.87 97.89 180 bottom
C217  100uF  [1206]  108.59 91.9 0 bottom
C218  10uF  [1210]  149.05 95.17 0 bottom
C219  10uF  [1210]  108.59 96.22 180 bottom
C220  0.1uF  [0402]  119.26 94.9 0 bottom
C221  0.1uF  [0402]  117.56 94.9 0 bottom
C222  10nF  [0402]  115.95 96.32 180 bottom
C223  0.1uF  [0402]  194.49 94.24 90 bottom
C224  10nF  [0402]  131.64 94.67 270 bottom
C225  10nF  [0402]  136.28 94.9 0 bottom
C226  0.1uF  [0402]  131.64 93.35 270 bottom
C227  100uF  [1206]  73.69 96.09 180 bottom
C228  10uF  [1210]  68.84 97.21 270 bottom
C229  0.1uF  [0402]  70.82 97.82 180 bottom
C230  10nF  [0402]  73.03 94.57 270 bottom
C231  1uF  [0402]  104.81 103.48 180 bottom
C232  0.1uF  [0402]  103.92 103.48 180 bottom
C233  0.1uF  [0402]  102.85 95.94 270 bottom
C234  10nF  [0402]  134.59 105.34 180 bottom
C235  0.1uF  [0402]  136.3 102.52 0 bottom
C236  10nF  [0402]  139.69 106.37 0 bottom
C237  0.1uF  [0402]  113.39 105.39 180 bottom
C238  10nF  [0402]  118.45 102.92 0 bottom
C239  0.1uF  [0402]  122.31 105.26 180 bottom
C240  10nF  [0402]  142.25 105.44 180 bottom
C241  0.1uF  [0402]  146.49 105.26 180 bottom
C242  10nF  [0402]  118.04 105.26 180 bottom
C243  0.1uF  [0402]  114.23 105.26 180 bottom
C244  10nF  [0402]  145.65 102.57 0 bottom
C245  0.1uF  [0402]  141.38 102.57 0 bottom
C246  100uF  [1206]  130.56 103.96 0 bottom
C247  1uF  [0402]  130.75 101.04 90 bottom
C248  0.1uF  [0402]  194.43 100.56 90 bottom
C249  0.1uF  [0402]  130.75 106.89 90 bottom
C250  0.1uF  [0402]  194.43 101.45 90 bottom
C251  10nF  [0402]  130.75 105.62 90 bottom
C252  100uF  [1206]  108.82 102.47 0 bottom
C253  100uF  [1206]  149.56 102.34 180 bottom
C254  10uF  [1210]  149.61 104.98 0 bottom
C255  10uF  [1210]  108.82 105.13 180 bottom
C256  0.1uF  [0402]  116.75 105.26 180 bottom
C257  0.1uF  [0402]  114.6 103.36 270 bottom
C258  10nF  [0402]  122.71 102.92 0 bottom
C259  10nF  [0402]  143.92 102.57 0 bottom
C260  0.1uF  [0402]  130.74 102.31 90 bottom
C261  100uF  [1206]  73.97 104.07 180 bottom
C262  10uF  [1210]  68 104.65 270 bottom
C263  0.1uF  [0402]  69.99 105.44 180 bottom
C264  10nF  [0402]  72.99 102.31 270 bottom
C265  0.1uF  [0402]  44.08 79.35 0 bottom
C266  22uF  [0603]  44.33 81.89 90 bottom
C267  0.1uF  [0402]  56.65 79.99 180 bottom
C268  10uF  [0603]  54.62 79.99 90 bottom
C269  22uF  [0603]  50.68 78.34 90 bottom
C270  22uF  [0603]  53.09 78.34 90 bottom
C271  0.1uF  [0402]  51.82 82.12 0 bottom
C272  10uF  [0603]  50.55 82.12 270 bottom
C273  22uF  [0603]  46.87 82.88 0 bottom
C274  22uF  [0603]  46.87 81.1 0 bottom
C275  0.1uF  [0402]  57.41 83.16 0 bottom
C276  10uF  [0603]  56.01 83.8 270 bottom
C277  22uF  [0603]  54.49 88.62 180 bottom
C278  22uF  [0603]  50.55 86.69 90 bottom
C279  1000pF  [1206]  19.82 70.94 270 bottom
C280  0.1uF  [0402]  44.08 54.56 0 bottom
C281  22uF  [0603]  44.33 57.1 90 bottom
C282  0.1uF  [0402]  56.65 55.2 180 bottom
C283  10uF  [0603]  55 55.2 90 bottom
C284  22uF  [0603]  53.22 53.55 90 bottom
C285  22uF  [0603]  50.68 53.55 90 bottom
C286  0.1uF  [0402]  50.68 57.36 0 bottom
C287  10uF  [0603]  49.41 57.48 270 bottom
C288  22uF  [0603]  46.87 57.86 0 bottom
C289  22uF  [0603]  46.87 56.34 0 bottom
C290  0.1uF  [0402]  57.41 58.37 0 bottom
C291  10uF  [0603]  56.01 58.88 270 bottom
C292  22uF  [0603]  50.68 62.05 90 bottom
C293  22uF  [0603]  52.71 58.12 0 bottom
C294  1000pF  [1206]  33.43 66.98 90 bottom
C295  1uF  [0402]  18.64 79.45 0 bottom
C296  0.1uF  [0402]  17.64 79.45 0 bottom
C297  1uF  [0402]  14.89 86.46 270 bottom
C298  0.1uF  [0402]  14.89 85.46 270 bottom
C299  1uF  [0402]  29.76 84.48 90 bottom
C300  0.1uF  [0402]  29.76 83.44 90 bottom
C301  1uF  [0402]  25.71 88.45 180 bottom
C302  0.1uF  [0402]  24.79 88.45 180 bottom
C303  1uF  [0402]  22.11 79.45 0 bottom
C304  0.1uF  [0402]  23.12 79.45 0 bottom
C305  2.2uF  [0402]  18.68 88.22 270 bottom
C306  0.22uF  [SMC0201IA]  62.83 10.73 270 bottom
C307  0.22uF  [SMC0201IA]  63.49 10.73 270 bottom
C308  1uF  [0402]  107.91 30.53 270 bottom
C309  0.1uF  [0402]  97.7 30.56 90 bottom
C310  0.1uF  [0402]  107.91 31.32 270 bottom
C311  0.22uF  [SMC0201IA]  67.83 10.73 270 bottom
C312  0.22uF  [SMC0201IA]  68.49 10.73 270 bottom
C313  0.22uF  [SMC0201IA]  71.83 10.73 270 bottom
C314  0.22uF  [SMC0201IA]  72.49 10.73 270 bottom
C315  0.22uF  [SMC0201IA]  75.83 10.73 270 bottom
C316  0.22uF  [SMC0201IA]  76.49 10.73 270 bottom
C317  0.22uF  [SMC0201IA]  81.83 10.73 270 bottom
C318  0.22uF  [SMC0201IA]  82.49 10.73 270 bottom
C319  1pF  [0402]  58.17 11 180 top
C320  0.22uF  [SMC0201IA]  85.83 10.73 270 bottom
C321  1pF  [0402]  65.03 11 0 bottom
C322  0.22uF  [SMC0201IA]  86.49 10.73 270 bottom
C323  1pF  [0402]  74.56 11 180 top
C324  1pF  [0402]  77.73 11 0 bottom
C325  1pF  [0402]  79.64 11 0 bottom
C326  0.22uF  [SMC0201IA]  89.83 10.73 270 bottom
C327  1pF  [0402]  125.48 11 180 top
C328  0.22uF  [SMC0201IA]  90.49 10.73 270 bottom
C329  1pF  [0402]  97.54 11 0 bottom
C330  1pF  [0402]  61.35 11 180 top
C331  1pF  [0402]  79.51 11 180 top
C332  0.22uF  [SMC0201IA]  93.83 10.73 270 bottom
C333  1pF  [0402]  95.77 11 180 top
C334  0.22uF  [SMC0201IA]  94.49 10.73 270 bottom
C335  1pF  [0402]  121.6 11 180 top
C336  0.22uF  [SMC0201IA]  98.83 10.73 270 bottom
C337  0.22uF  [SMC0201IA]  99.49 10.73 270 bottom
C338  0.22uF  [SMC0201IA]  102.83 10.73 270 bottom
C339  0.22uF  [SMC0201IA]  103.49 10.73 270 bottom
C340  0.1uF  [0402]  57.16 15.7 270 bottom
C341  0.22uF  [SMC0201IA]  106.83 10.73 270 bottom
C342  0.22uF  [SMC0201IA]  107.49 10.73 270 bottom
C343  0.22uF  [SMC0201IA]  110.83 10.73 270 bottom
C344  0.22uF  [SMC0201IA]  111.49 10.73 270 bottom
C345  0.22uF  [SMC0201IA]  114.83 10.73 270 bottom
C346  0.22uF  [SMC0201IA]  115.49 10.73 270 bottom
C347  0.22uF  [SMC0201IA]  118.83 10.73 270 bottom
C348  0.22uF  [SMC0201IA]  119.49 10.73 270 bottom
C349  0.22uF  [SMC0201IA]  122.83 10.73 270 bottom
C350  0.22uF  [SMC0201IA]  123.49 10.73 270 bottom
C351  0.22uF  [SMC0201IA]  126.83 10.73 270 bottom
C352  0.22uF  [SMC0201IA]  127.49 10.73 270 bottom
C353  0.1uF  [0402]  56.01 13.03 270 bottom
C354  0.22uF  [SMC0201IA]  211.9 17.14 0 top
C355  0.22uF  [SMC0201IA]  211.9 17.8 0 top
C356  0.22uF  [SMC0201IA]  212.86 18.95 0 top
C357  0.22uF  [SMC0201IA]  212.86 19.61 0 top
C358  0.22uF  [SMC0201IA]  211.75 24.39 0 top
C359  0.22uF  [SMC0201IA]  211.75 25.05 0 top
C360  0.22uF  [SMC0201IA]  212.86 26.15 0 top
C361  0.22uF  [SMC0201IA]  212.86 26.81 0 top
C362  0.22uF  [SMC0201IA]  210.88 27.95 0 top
C363  0.22uF  [SMC0201IA]  210.88 28.61 0 top
C364  0.22uF  [SMC0201IA]  212.86 29.75 0 top
C365  0.22uF  [SMC0201IA]  212.86 30.41 0 top
C366  0.22uF  [SMC0201IA]  210.88 35.15 0 top
C367  0.22uF  [SMC0201IA]  210.88 35.81 0 top
C368  0.22uF  [SMC0201IA]  212.86 36.95 0 top
C369  0.22uF  [SMC0201IA]  212.86 37.61 0 top
C370  1uF  [0402]  208.41 89.18 0 bottom
C371  0.1uF  [0402]  207.4 89.18 0 bottom
C372  0.1uF  [0402]  197.85 88.64 90 bottom
C373  0.22uF  [SMC0201IA]  210.88 45.86 0 top
C374  0.22uF  [SMC0201IA]  210.88 46.52 0 top
C375  0.22uF  [SMC0201IA]  212.86 47.66 0 top
C376  0.22uF  [SMC0201IA]  212.86 48.32 0 top
C377  0.22uF  [SMC0201IA]  210.88 53.06 0 top
C378  0.22uF  [SMC0201IA]  210.88 53.72 0 top
C379  0.22uF  [SMC0201IA]  212.86 54.86 0 top
C380  0.22uF  [SMC0201IA]  212.86 55.52 0 top
C381  0.22uF  [SMC0201IA]  210.88 56.66 0 top
C382  0.22uF  [SMC0201IA]  210.88 57.32 0 top
C383  0.22uF  [SMC0201IA]  212.86 58.46 0 top
C384  0.22uF  [SMC0201IA]  212.86 59.12 0 top
C385  0.22uF  [SMC0201IA]  210.88 63.86 0 top
C386  0.22uF  [SMC0201IA]  210.88 64.52 0 top
C387  0.22uF  [SMC0201IA]  212.86 65.66 0 top
C388  0.22uF  [SMC0201IA]  212.86 66.32 0 top
C389  0.1uF  [0402]  139.22 36.17 180 bottom
C390  0.1uF  [0402]  6.43 24.41 180 top
C391  0.1uF  [0402]  6.91 24.14 270 bottom
C392  0.1uF  [0402]  99.58 83.14 90 bottom
C393  0.1uF  [0402]  122.75 59.39 180 bottom
C394  10uF  [0603]  150.76 46.94 0 bottom
C395  0.47uF  [0402]  148.72 45.67 180 bottom
C396  4.7uF  [0402]  127.04 53.37 120 bottom
C397  1uF  [0201]  105.47 65.54 30 bottom
C404  47uF  [0603]  87.56 71.44 0 bottom
C405  22uF  [0603]  87.56 69.74 180 bottom
C406  47uF  [0603]  86.39 73.14 180 bottom
C407  47uF  [0603]  87.56 57.1 0 bottom
C408  47uF  [0603]  87.56 60.4 0 bottom
C409  47uF  [0603]  87.56 58.88 0 bottom
C410  47uF  [0603]  87.56 47.34 0 bottom
C411  47uF  [0603]  87.56 50.49 0 bottom
C412  22uF  [0603]  87.56 48.91 180 bottom
C413  47uF  [0603]  87.56 64.14 0 bottom
C414  47uF  [0603]  87.56 62.14 0 bottom
C415  22uF  [0603]  85.26 63.64 270 bottom
C416  1uF  [0201]  108.85 66.57 30 bottom
C417  0.1uF  [0402]  110.33 47.11 120 bottom
C418  0.1uF  [0402]  111.98 47.11 120 bottom
C419  0.1uF  [0402]  119.86 47.16 120 bottom
C420  0.1uF  [0402]  122.36 47.19 240 bottom
C421  0.1uF  [0402]  110.31 71.61 60 bottom
C422  0.1uF  [0402]  112.78 71.61 300 bottom
C423  0.1uF  [0402]  116.46 85.67 180 top
C424  0.1uF  [0402]  115.6 85.67 180 top
C425  1uF  [0402]  51.42 21.87 270 bottom
C426  1uF  [0402]  51.42 22.76 270 bottom
C427  1uF  [0402]  52.2 28.3 270 bottom
C428  1uF  [0402]  57.56 27.49 90 bottom
C429  1uF  [0402]  51.42 25.86 270 bottom
C430  1uF  [0402]  57.56 23.83 90 bottom
C431  1uF  [0402]  57.56 28.65 90 bottom
C432  1uF  [0402]  53.34 27.17 180 bottom
C433  1uF  [0402]  57.56 22.81 90 bottom
C434  1uF  [0402]  58.17 17.92 270 bottom
C435  1uF  [0402]  57.41 20.14 0 bottom
C436  1uF  [0402]  56.4 20.14 0 bottom
C437  1uF  [0402]  51.42 23.83 270 bottom
C438  1uF  [0402]  60.08 27.87 270 bottom
C439  1uF  [0402]  51.42 24.84 270 bottom
C440  1uF  [0402]  51.44 27 270 bottom
C441  1uF  [0402]  56.01 27.16 180 bottom
C442  1uF  [0402]  57.56 24.84 90 bottom
C443  1uF  [0402]  57.56 26.29 90 bottom
C444  1uF  [0402]  54.77 27.21 180 bottom
C445  0.1uF  [0402]  61.22 23.97 90 top
C446  0.1uF  [0402]  61.22 22.95 90 top
C447  0.1uF  [0402]  61.25 22 90 top
C448  0.1uF  [0402]  61.25 20.98 90 top
C451  0.1uF  [0402]  55.87 30.94 180 top
C452  0.1uF  [0402]  56.89 30.94 180 top
C453  0.1uF  [0402]  52 30.94 180 top
C454  0.1uF  [0402]  52.97 30.94 180 top
C455  18pF  [0402]  43.44 39.96 180 top
C456  1uF  [0402]  46.62 41.23 180 bottom
C457  0.1uF  [0402]  45.22 38.5 270 bottom
C458  0.1uF  [0402]  50.55 40.21 90 bottom
C459  0.1uF  [0402]  47.63 41.23 180 bottom
C460  1uF  [0402]  45.22 37.48 270 bottom
C461  1uF  [0402]  50.55 37.8 90 bottom
C462  0.1uF  [0402]  49.16 35.89 0 bottom
C463  4.7uF  [0402]  44.33 43.13 270 bottom
C464  18pF  [0402]  43.44 38.05 0 top
C465  0.1uF  [0402]  55.89 33.18 180 top
C466  0.1uF  [0402]  56.9 33.18 180 top
C467  0.1uF  [0402]  59.57 32.97 180 top
C468  0.1uF  [0402]  60.59 32.97 180 top
C471  1uF  [0402]  208.36 59.31 90 bottom
C472  1uF  [0402]  210.27 67.62 90 bottom
C473  0.1uF  [0402]  214.51 55.2 0 bottom
C474  0.1uF  [0402]  213.49 55.2 0 bottom
C475  0.1uF  [0402]  210.64 55.72 0 bottom
C476  0.1uF  [0402]  209.76 55.72 0 bottom
C477  0.1uF  [0402]  17.45 107.19 180 top
C478  0.1uF  [0402]  16.63 108.72 90 top
C479  0.1uF  [0402]  16.33 104.22 270 bottom
C480  0.1uF  [0402]  17.24 102.44 180 top
C481  0.1uF  [0402]  31 100.66 180 bottom
C482  0.1uF  [0402]  31 93.55 180 bottom
C483  0.1uF  [0402]  66.05 35 270 bottom
C484  0.1uF  [0402]  55.38 35.26 90 bottom
C485  0.1uF  [0402]  47.45 22.84 90 top
C486  0.1uF  [0402]  46.36 31.98 0 top
C487  0.1uF  [0402]  24.39 100.79 180 bottom
C488  0.1uF  [0402]  24.39 93.42 180 bottom
C489  0.1uF  [0402]  17.53 100.79 180 bottom
C490  0.1uF  [0402]  17.53 93.42 180 bottom
C491  1000pF  [0402]  247.02 65.74 0 bottom
C492  1000pF  [0402]  246.9 62.69 180 bottom
C493  1000pF  [0402]  246.9 57.61 0 bottom
C494  DNI  [1206]  242.01 105.26 270 bottom
C495  0.1uF  [0402]  36.96 35.44 0 bottom
C496  4.7nF  [0402]  6.05 26.14 90 top
C497  12pF  [0402]  11.46 22.05 0 top
C498  0.1uF  [0402]  41.89 16.92 180 top
C499  0.1uF  [0402]  7.32 32.21 270 top
C500  2.2uF  [0603]  40.39 15.11 90 top
C501  0.1uF  [0402]  39.3 15.01 180 top
C502  22uF  [0603]  12.07 25.96 90 bottom
C503  0.1uF  [0402]  16.73 25.56 0 bottom
C504  0.1uF  [0402]  13.98 25.86 0 bottom
C505  0.1uF  [0402]  17.86 26.75 90 bottom
C506  0.1uF  [0402]  18.55 31.88 90 bottom
C507  0.1uF  [0402]  19.97 32.32 0 bottom
C508  0.1uF  [0402]  16.12 32.57 180 bottom
C509  0.1uF  [0402]  10.85 32.36 270 bottom
C510  0.1uF  [0402]  19.57 26.75 270 bottom
C512  0.1uF  [0402]  17.26 15.33 270 top
C513  100uF  [C2012]  22.44 30.99 270 bottom
C514  0.1uF  [0402]  32.79 26.5 0 bottom
C515  0.1uF  [0402]  29.47 25.48 0 bottom
C516  0.1uF  [0402]  32.8 24.11 315 bottom
C517  0.1uF  [0402]  31.35 24.36 180 bottom
C518  0.1uF  [0402]  31.5 27.61 0 bottom
C519  0.1uF  [0402]  30.11 24.46 135 bottom
C520  0.1uF  [0402]  32.17 25.38 225 bottom
C521  0.1uF  [0402]  30.49 26.39 0 bottom
C522  0.1uF  [0402]  28.05 25.83 90 bottom
C523  10uF  [0603]  23.76 34.98 0 bottom
C524  0.1uF  [0402]  34.85 22.29 315 bottom
C525  0.1uF  [0402]  27.81 23.22 315 bottom
C526  0.1uF  [0402]  27.5 30.4 0 bottom
C527  0.1uF  [0402]  35 28.86 270 bottom
C528  0.1uF  [0402]  27.95 29.03 270 bottom
C529  0.1uF  [0402]  26 24.9 90 bottom
C530  0.1uF  [0402]  26 26.9 90 bottom
C531  0.1uF  [0402]  31 29.92 270 bottom
C532  0.1uF  [0402]  26.3 22.43 180 bottom
C533  0.1uF  [0402]  28.23 20.68 135 bottom
C534  0.1uF  [0402]  21.02 20.01 90 bottom
C535  0.1uF  [0402]  21.02 20.81 90 bottom
C536  0.1uF  [0402]  29.47 20.4 180 bottom
C537  0.1uF  [0402]  26 25.9 90 bottom
C538  0.1uF  [0402]  26 23.9 90 bottom
C539  0.1uF  [0402]  33.48 30.41 0 bottom
C540  0.1uF  [0402]  29.06 29.9 90 bottom
C541  10uF  [0603]  20.87 29.58 270 bottom
C542  0.1uF  [0402]  35 20.89 90 bottom
C543  0.1uF  [0402]  27 21.39 135 bottom
C544  0.1uF  [0402]  35.22 30.13 45 bottom
C545  0.1uF  [0402]  26 29.9 90 bottom
C546  0.1uF  [0402]  28.46 27.49 180 bottom
C547  10uF  [0603]  32.85 15.64 225 bottom
C548  0.1uF  [0402]  32.49 20.48 180 bottom
C549  0.1uF  [0402]  33.48 20.48 180 bottom
C550  10uF  [0603]  21.34 23.45 90 bottom
C551  0.1uF  [0402]  31 20.91 270 bottom
C552  0.1uF  [0402]  21.02 19.21 90 bottom
C553  0.1uF  [0402]  32.49 29.49 180 bottom
C554  0.1uF  [0402]  30 30.9 270 bottom
C555  0.1uF  [0402]  22.77 23.13 0 bottom
C556  0.1uF  [0402]  21.02 21.61 90 bottom
C557  0.1uF  [0402]  36.08 61.17 0 bottom
C558  0.1uF  [0402]  53.22 13.79 270 bottom
C559  0.1uF  [0402]  37.35 50.9 270 bottom
C560  0.1uF  [0402]  47.89 12.02 180 bottom
C561  0.1uF  [0402]  247.02 47.2 270 bottom
C562  0.1uF  [0402]  244.1 53.42 90 bottom
C563  100pf  [0402]  69.95 81.13 0 top
C564  100pf  [0402]  69.95 79.23 0 top
C565  0.1uF  [0402]  72.1 79.23 270 bottom
C566  100pf  [0402]  73.12 77.89 90 top
C567  0.1uF  [0402]  33.54 62.69 0 bottom
C568  100pf  [0402]  167.42 90.5 0 bottom
C569  100pf  [0402]  167.42 92.41 0 bottom
C570  0.1uF  [0402]  167.44 89.06 90 bottom
C571  100pf  [0402]  170.62 93.98 270 bottom
C572  680pF  [0402]  245.29 90.12 90 bottom
C573  1uF  [0402]  245.29 91.14 270 bottom
C574  560uF  [8MM_CAN]  232.04 76.91 270 top
C575  22uF  [1206]  230.89 75.64 0 bottom
C576  22uF  [1206]  230.89 80.72 0 bottom
C577  22uF  [1206]  230.89 73.1 0 bottom
C578  22uF  [1206]  230.89 78.18 0 bottom
C579  4.7nF  [0402]  240.86 80.6 90 bottom
C580  DNI  [7343P]  224.54 82.88 270 top
C581  4.7nF  [0402]  217.05 87.71 180 top
C582  1.5uF  [1206]  216.67 84.79 90 bottom
C583  150uF  [7343P_H2MM]  230.03 69.65 180 bottom
C584  150uF  [7343P]  239.4 69.67 0 top
C585  150uF  [7343P]  229.5 69.67 180 top
C586  150uF  [7343P_H2MM]  169.7 33.3 180 bottom
C587  0.01uF  [0402]  217.18 90.38 90 bottom
C588  150uF  [7343P]  205.24 72.85 180 top
C589  4.7nF  [0402]  212.35 79.07 0 bottom
C590  DNI  [7343P]  220.86 73.99 0 top
C591  150uF  [7343P_H2MM]  205.54 75.8 180 bottom
C592  150uF  [7343P]  205.29 82.65 180 top
C593  150uF  [7343P]  205.29 77.84 180 top
C594  150uF  [7343P_H2MM]  240.75 49.51 270 bottom
C595  150uF  [7343P_H2MM]  205.57 85.32 180 bottom
C596  150uF  [7343P_H2MM]  205.54 80.5 180 bottom
C597  0.1uF  [0402]  237.62 74.12 180 top
C618  22uF  [1206]  187.64 44.04 270 bottom
C715  1uF  [0402]  235.69 63.41 0 bottom
C716  0.1uF  [0402]  233.79 64.21 0 bottom
C717  22uF  [1206]  241.43 64.47 90 top
C718  22uF  [1206]  238.89 64.47 90 bottom
C719  22uF  [1206]  238.89 64.47 90 top
C720  12pF  [0402]  229.37 60.51 270 bottom
C721  47uF  [1206]  238.89 59.64 90 bottom
C722  47uF  [1206]  238.89 59.64 90 top
C723  47uF  [1206]  241.43 59.64 90 bottom
C724  47uF  [1206]  241.43 59.64 90 top
C725  100pf  [0402]  232.93 58.85 90 top
C726  0.1uF  [0402]  229.37 61.32 270 bottom
C727  DNI  [C0402]  231.16 57.71 90 top
C783  47UF  [1206]  133.66 87.65 270 bottom
C784  22uF  [1206]  138.75 87.65 90 bottom
C785  22uF  [1206]  136.25 87.65 90 bottom
C804  0.1uF  [0402]  39.4 105.82 180 top
C805  22pF  [0603]  41.43 105.95 0 top
C806  4700pF  [0603]  45.12 105.31 270 top
C807  330pF  [0402]  44.86 102.9 0 top
C808  0.1uF  [0402]  34.83 103.53 270 top
C809  10uF  [0402]  43.21 102.64 90 top
C810  10uF  [0805]  33.18 99.72 180 top
C811  4.7uF  [0603]  35.08 99.72 90 top
C812  10uF  [0805]  44.86 99.72 180 top
C813  4.7uF  [0603]  42.96 99.72 90 top
C814  150uF  [7343P_H2MM]  36.61 100.99 0 bottom
C815  100uF  [0805]  43.47 94.64 0 bottom
C816  100uF  [0805]  33.31 94.71 0 bottom
C817  47uF  [0603]  36.23 94.71 90 bottom
C818  330uf  [1210]  33.81 95.15 270 top
C819  47uF  [0603]  40.29 94.64 90 bottom
C820  330uf  [1210]  44.23 95.28 270 top
C821  0.1uF  [0402]  209.18 35.77 180 top
C822  22pF  [0603]  208.92 33.4 90 top
C823  4700pF  [0603]  211.11 32.64 180 top
C824  330pF  [0402]  207.65 29.64 270 top
C825  0.1uF  [0402]  207.14 39.45 180 top
C826  10uF  [0402]  206.26 31.07 0 top
C827  10uF  [0805]  206 36.91 0 bottom
C828  4.7uF  [0603]  203.33 31.34 0 top
C829  10uF  [0805]  203.33 29.75 90 top
C830  4.7uF  [0603]  203.33 39.32 0 top
C831  150uF  [7343P_H2MM]  202.19 35 270 bottom
C832  330uf  [1210]  198.69 39.14 180 top
C833  100uF  [0805]  197.7 37.16 270 bottom
C834  330uf  [1210]  198.38 31.14 180 top
C835  100uF  [0805]  197.64 31.83 270 bottom
C837  47uF  [0603]  197.68 33.73 0 bottom
C838  47uF  [0603]  197.68 35.26 0 bottom
C891  10uF  [0603]  87.56 67.34 0 bottom
C892  0.47uF  [0402]  87.51 65.86 270 bottom
C977  2.2uF  [0402]  46.06 29.35 90 top
C978  22uF  [0603]  39.58 25.73 180 bottom
C979  22uF  [0603]  39.58 24.41 180 bottom
C980  22uF  [0603]  39.58 23.09 180 bottom
C981  22uF  [0603]  42.78 30.1 0 top
C982  22uF  [0603]  42.78 31.42 0 top
C983  0.1uF  [0402]  44.98 24.51 270 top
C984  22uF  [0603]  39.58 27.04 180 bottom
C985  0.01uF  [0402]  39.66 28.7 180 bottom
C986  2.2uF  [0402]  23.46 107.89 180 top
C987  22uF  [0603]  29 104.5 90 top
C988  22uF  [0603]  29 104.64 90 bottom
C989  22uF  [0603]  30.53 104.5 90 top
C990  22uF  [0603]  30.37 104.64 90 bottom
C991  22uF  [0603]  26.9 102.42 180 bottom
C992  22uF  [0603]  29.76 102.42 0 bottom
C993  22uF  [0603]  22.75 105.3 90 top
C994  22uF  [0603]  21.43 105.3 90 top
C995  22uF  [0603]  26.9 102.42 180 top
C996  22uF  [0603]  29.76 102.42 0 top
C997  0.1uF  [0402]  29.52 107.89 90 top
C998  0.01uF  [0402]  21.65 107.89 180 top
C1004  100uF  [B2]  40.77 78.18 270 bottom
C1005  DNI  [1210]  37.22 78.18 270 bottom
C1006  0.047uF  [0402]  34.61 81.49 90 bottom
C1019  22uF  [0402]  107.97 53.19 120 bottom
C1020  22uF  [0402]  119.01 67.1 300 bottom
C1021  22uF  [0402]  114.31 67.03 300 bottom
C1022  22uF  [0402]  115.11 69.27 300 bottom
C1023  22uF  [0402]  111.95 66.53 120 bottom
C1024  22uF  [0402]  109.56 59.63 120 bottom
C1025  22uF  [0402]  109.43 51.46 120 bottom
C1026  22uF  [0402]  107.97 55.03 120 bottom
C1027  22uF  [0402]  109.56 54.11 120 bottom
C1028  22uF  [0402]  115.19 52.56 300 bottom
C1029  22uF  [0402]  119.99 50.45 240 bottom
C1030  22uF  [0402]  121.52 52.82 120 bottom
C1031  22uF  [0402]  116.82 52.59 120 bottom
C1032  22uF  [0402]  108.77 62.85 120 bottom
C1033  22uF  [0402]  108.77 57.33 120 bottom
C1034  1uF  [0201]  105.66 62.32 330 bottom
C1035  1uF  [0201]  106.46 58.75 30 bottom
C1036  1uF  [0201]  107.25 61.05 30 bottom
C1037  22uF  [0402]  115.94 49.51 120 bottom
C1038  22uF  [0402]  123.88 55.93 300 bottom
C1039  22uF  [0402]  123.88 64.31 300 bottom
C1040  22uF  [0402]  124.65 66.61 300 bottom
C1041  1uF  [0201]  105.66 64.16 330 bottom
C1042  1uF  [0201]  111.24 69.22 330 bottom
C1043  1uF  [0201]  104.37 65.48 90 bottom
C1044  22uF  [0402]  114.27 50.53 120 bottom
C1045  10uF  [0402]  84.39 53.14 90 top
C1046  10uF  [0402]  84.39 69.14 270 top
C1047  10uF  [0402]  82.39 69.14 270 top
C1048  22uF  [0402]  123.93 53.02 300 bottom
C1049  22uF  [0402]  115.91 66.05 300 bottom
C1050  22uF  [0402]  109.95 64.92 180 bottom
C1051  22uF  [0402]  111.85 52.85 120 bottom
C1052  22uF  [0402]  112.72 49.53 120 bottom
C1053  22uF  [0402]  123.83 56.85 120 bottom
C1054  22uF  [0402]  120.18 68.17 0 bottom
C1055  22uF  [0402]  118.3 69.3 300 bottom
C1056  22uF  [0402]  120.78 65.86 300 bottom
C1057  22uF  [0402]  123.85 61.55 300 bottom
C1058  10uF  [0402]  106.38 60.07 60 bottom
C1059  10uF  [0402]  107.12 64.69 120 bottom
C1060  10uF  [0402]  105.58 57.33 120 bottom
C1061  47uF  [0603]  83.39 56.44 180 top
C1062  47uF  [0603]  83.27 67.84 180 top
C1063  100uF  [0805]  112.72 63.71 270 bottom
C1064  100uF  [0805]  120.25 55.58 90 bottom
C1065  100uF  [0805]  120.25 61.55 90 bottom
C1066  100uF  [0805]  120.25 63.71 90 bottom
C1067  100uF  [0805]  112.72 61.55 270 bottom
C1068  100uF  [0805]  112.78 57.74 270 bottom
C1069  100uF  [0805]  120.25 57.74 90 bottom
C1070  100uF  [0805]  112.78 55.58 270 bottom
C1090  47uF  [0603]  117.48 54.94 90 bottom
C1091  47uF  [0603]  112.78 59.64 0 bottom
C1092  47uF  [0603]  120.28 59.64 180 bottom
C1093  47uF  [0603]  116.76 63.83 270 bottom
C1094  10uF  [0402]  123.13 50.48 240 bottom
C1095  10uF  [0402]  122.41 51.86 60 bottom
C1096  10uF  [0402]  122.33 50 60 bottom
C1097  10uF  [0402]  123.96 51.01 60 bottom
C1098  10uF  [0402]  102.78 62.59 0 bottom
C1099  10uF  [0402]  103.62 64.89 0 bottom
C1100  10uF  [0402]  103.57 60.32 180 bottom
C1101  47uF  [0603]  83.27 66.14 180 top
C1102  47uF  [0603]  83.39 73.14 180 top
C1103  47uF  [0603]  83.39 74.84 180 top
C1104  47uF  [0603]  83.39 71.44 180 top
C1105  100uF  [0805]  105.32 85.7 270 top
C1106  100uF  [0805]  96.24 85.87 270 top
C1107  100uF  [0805]  128.68 87.58 180 top
C1108  100uF  [0805]  109.55 33.19 270 top
C1109  100uF  [0805]  123.15 33.07 90 top
C1110  100uF  [0805]  117.1 33.23 270 top
C1111  10uF  [0402]  128.66 60.09 60 bottom
C1112  10uF  [0402]  131.08 57.77 240 bottom
C1113  47uF  [0603]  83.34 50.84 180 top
C1114  10uF  [0402]  128.66 56.85 300 bottom
C1115  10uF  [0402]  104.88 52.17 300 bottom
C1116  47uF  [0603]  144.94 55.5 180 bottom
C1117  47uF  [0603]  125.14 85.4 0 top
C1118  47uF  [0603]  149.36 60.78 0 top
